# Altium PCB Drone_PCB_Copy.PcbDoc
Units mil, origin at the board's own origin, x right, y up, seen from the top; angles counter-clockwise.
Board outline 3300 x 3300 mil, 4 copper layers (Top Layer, Ground_Layer, Power_Layer, Bottom Layer), stack 40.247 mil thick; 10 components, 3 nets, 104 pads, 42 vias.
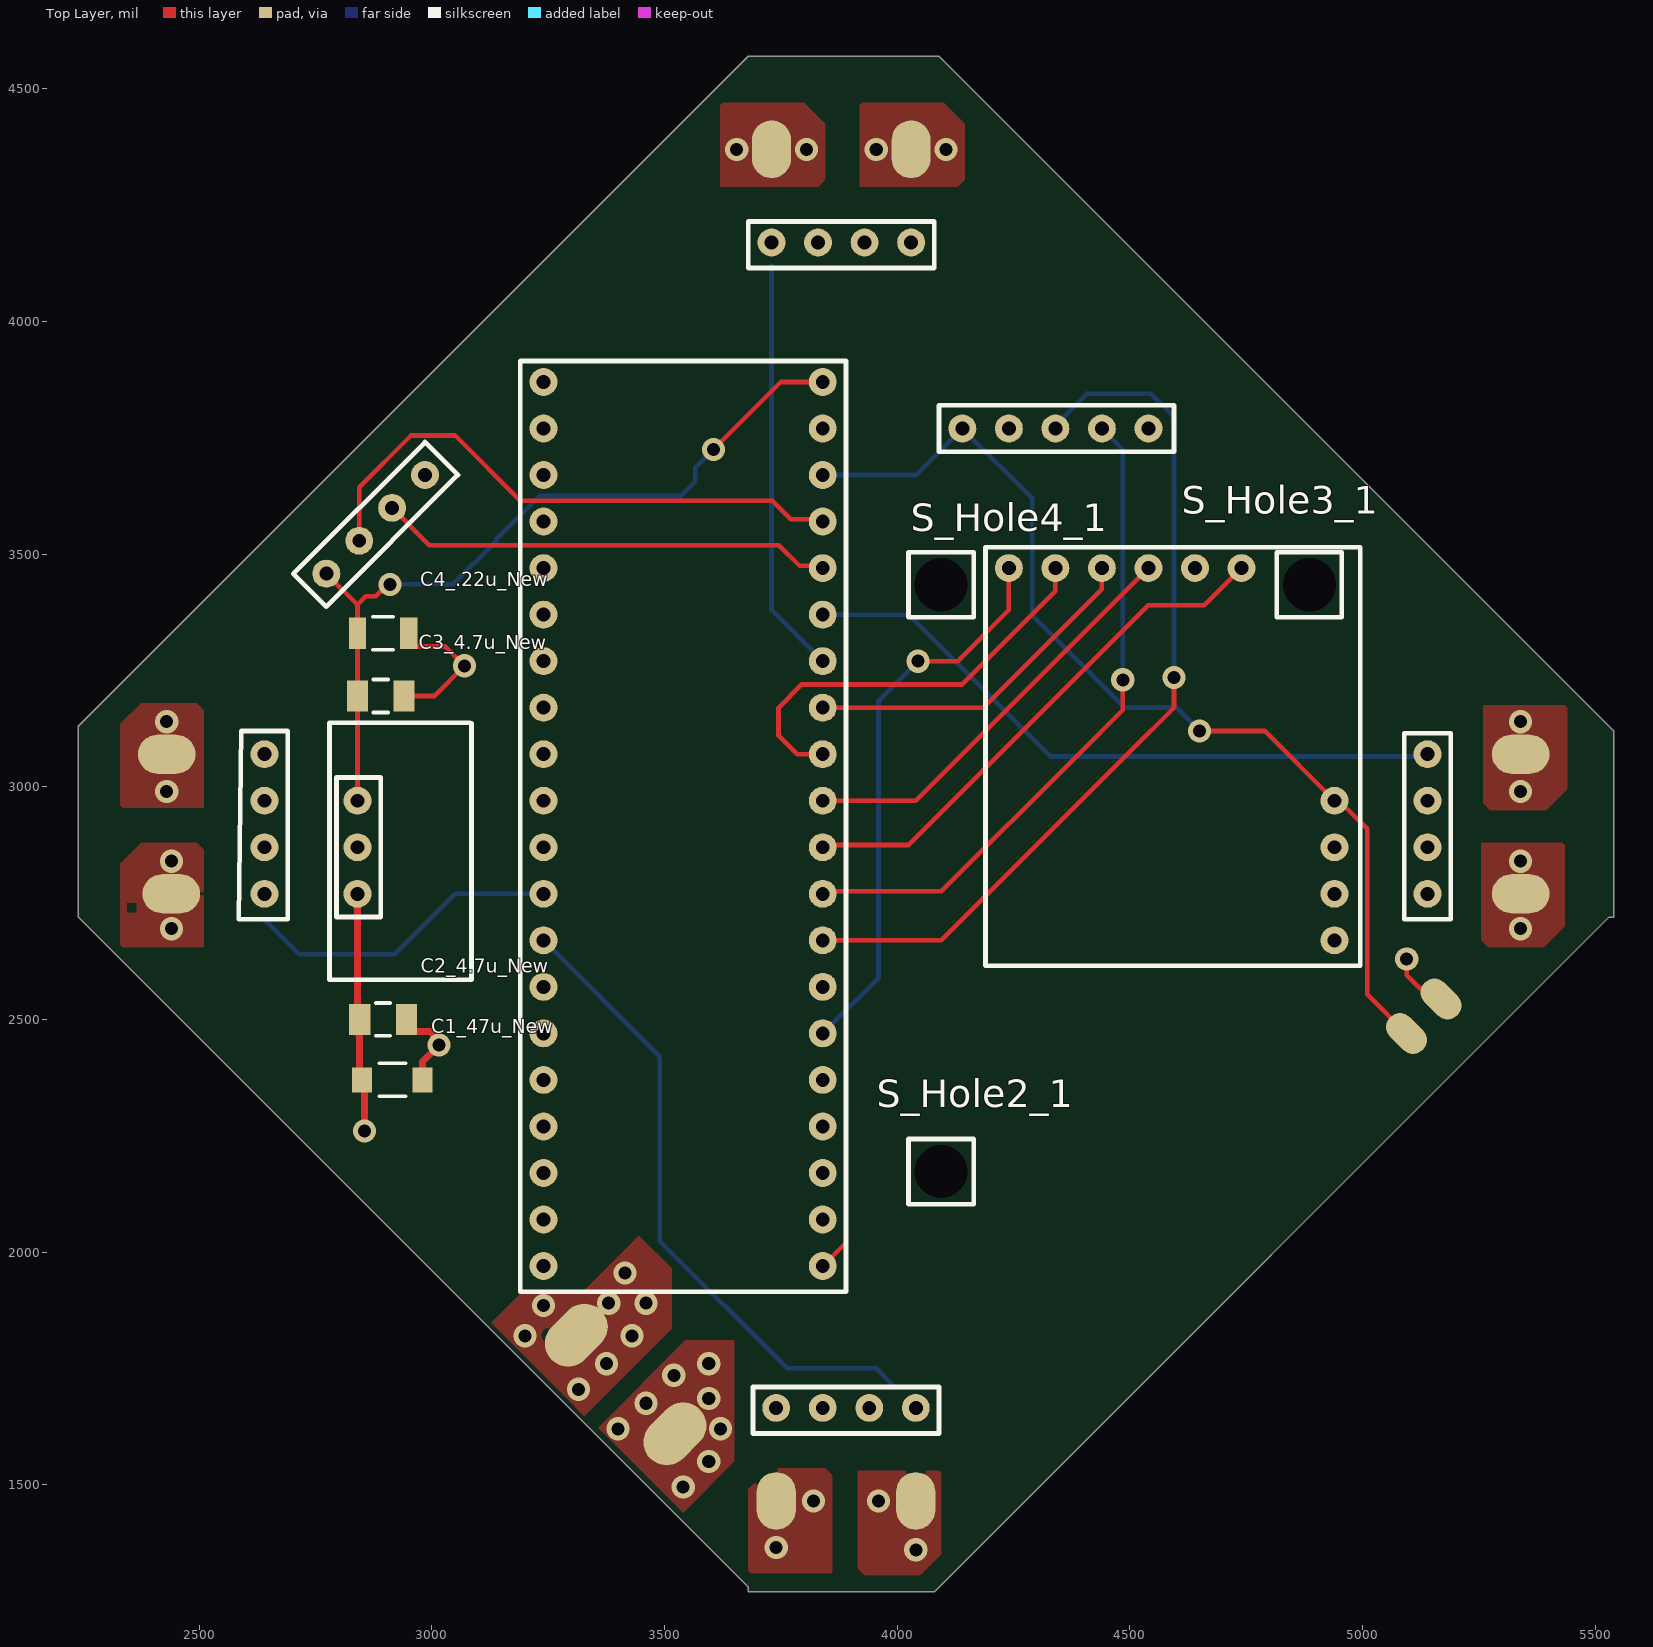
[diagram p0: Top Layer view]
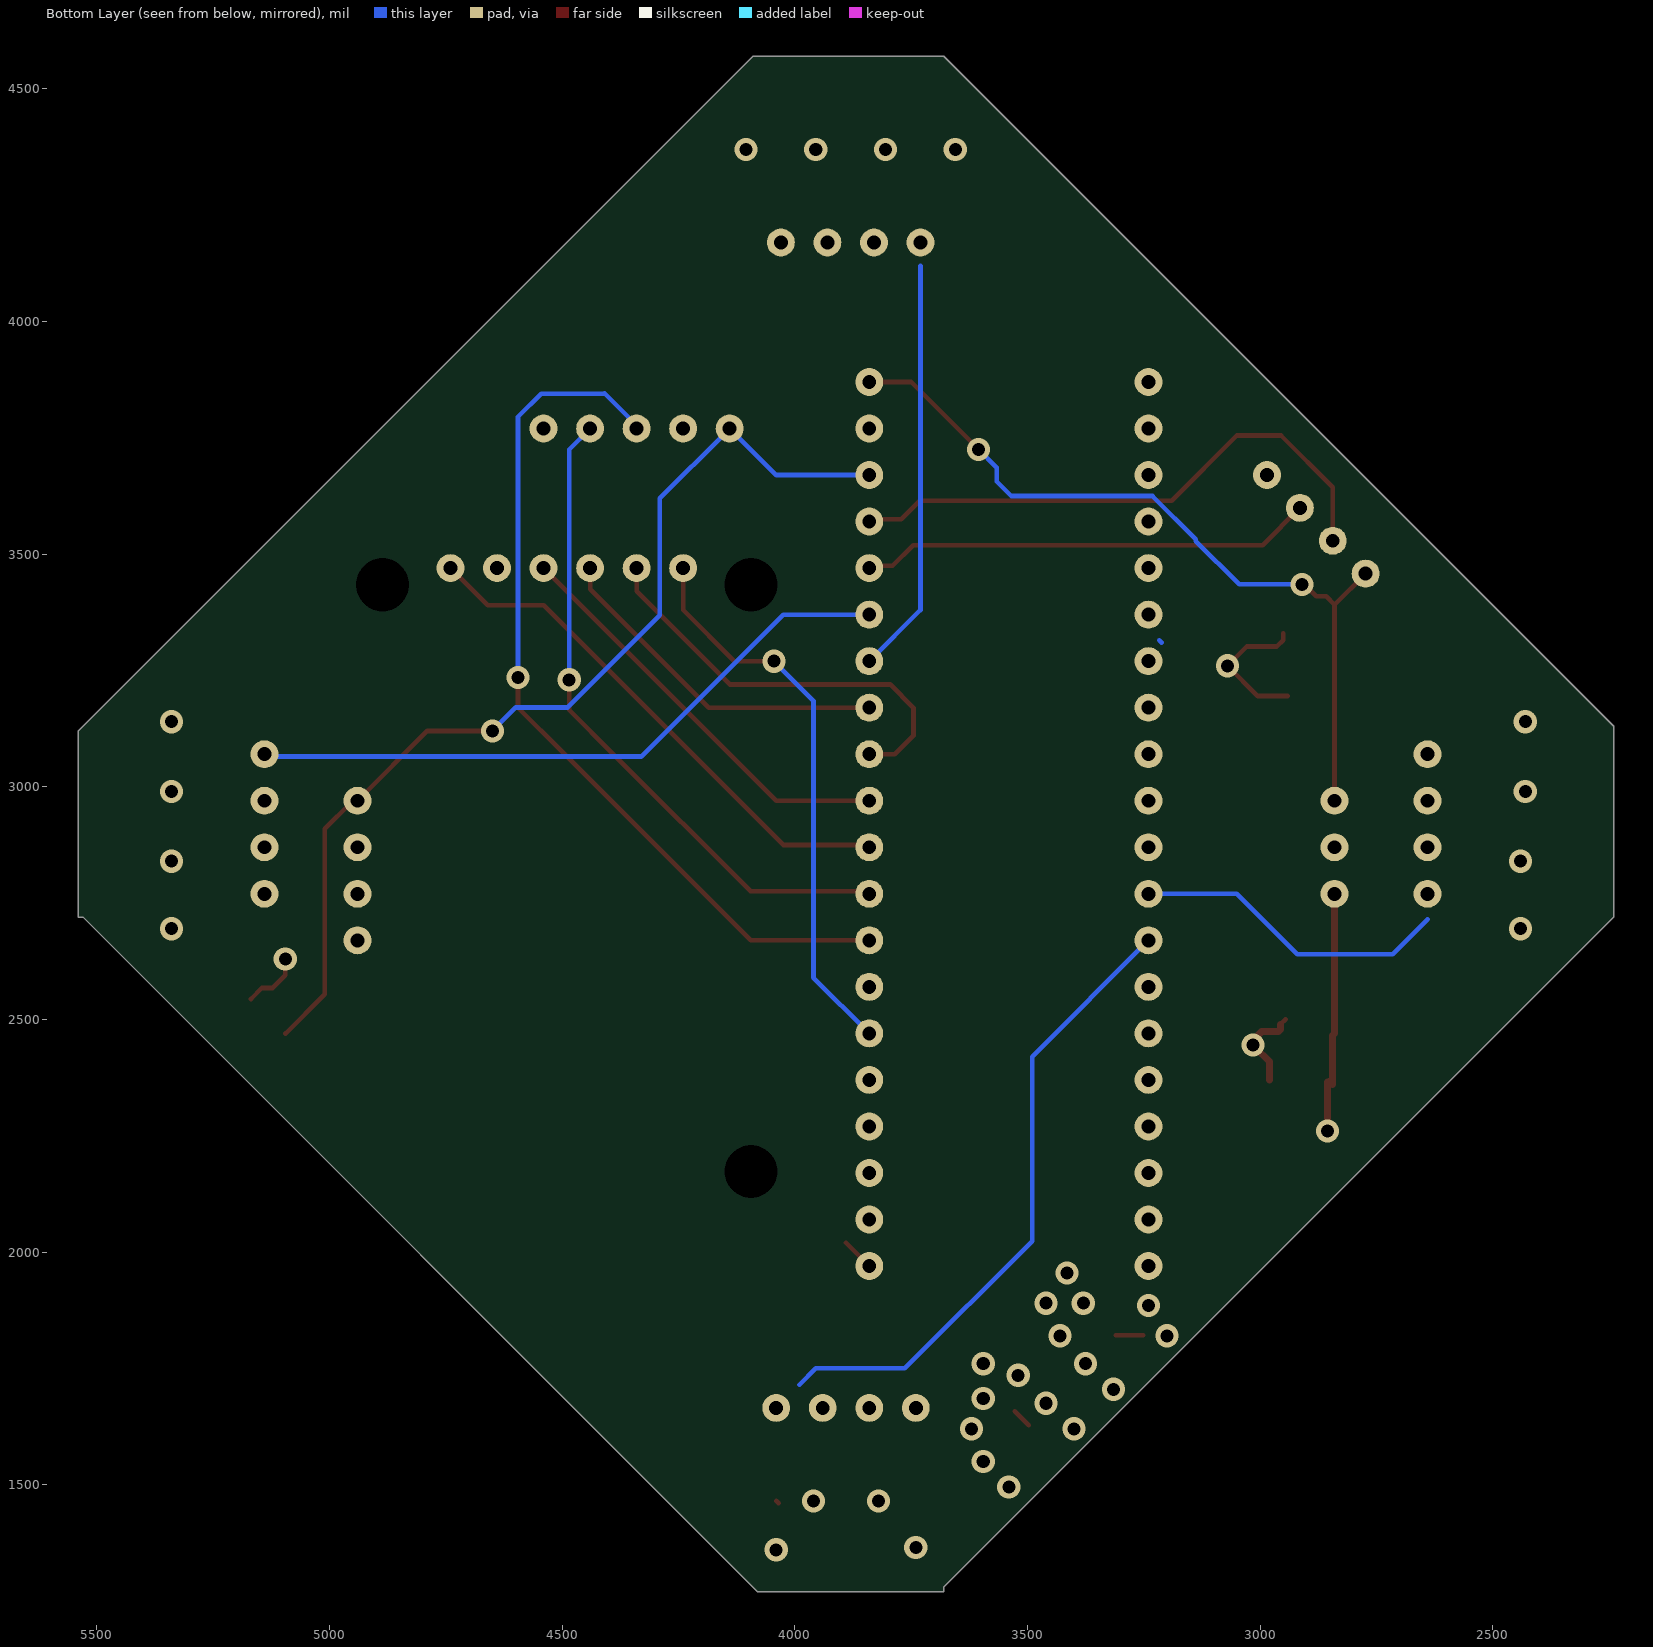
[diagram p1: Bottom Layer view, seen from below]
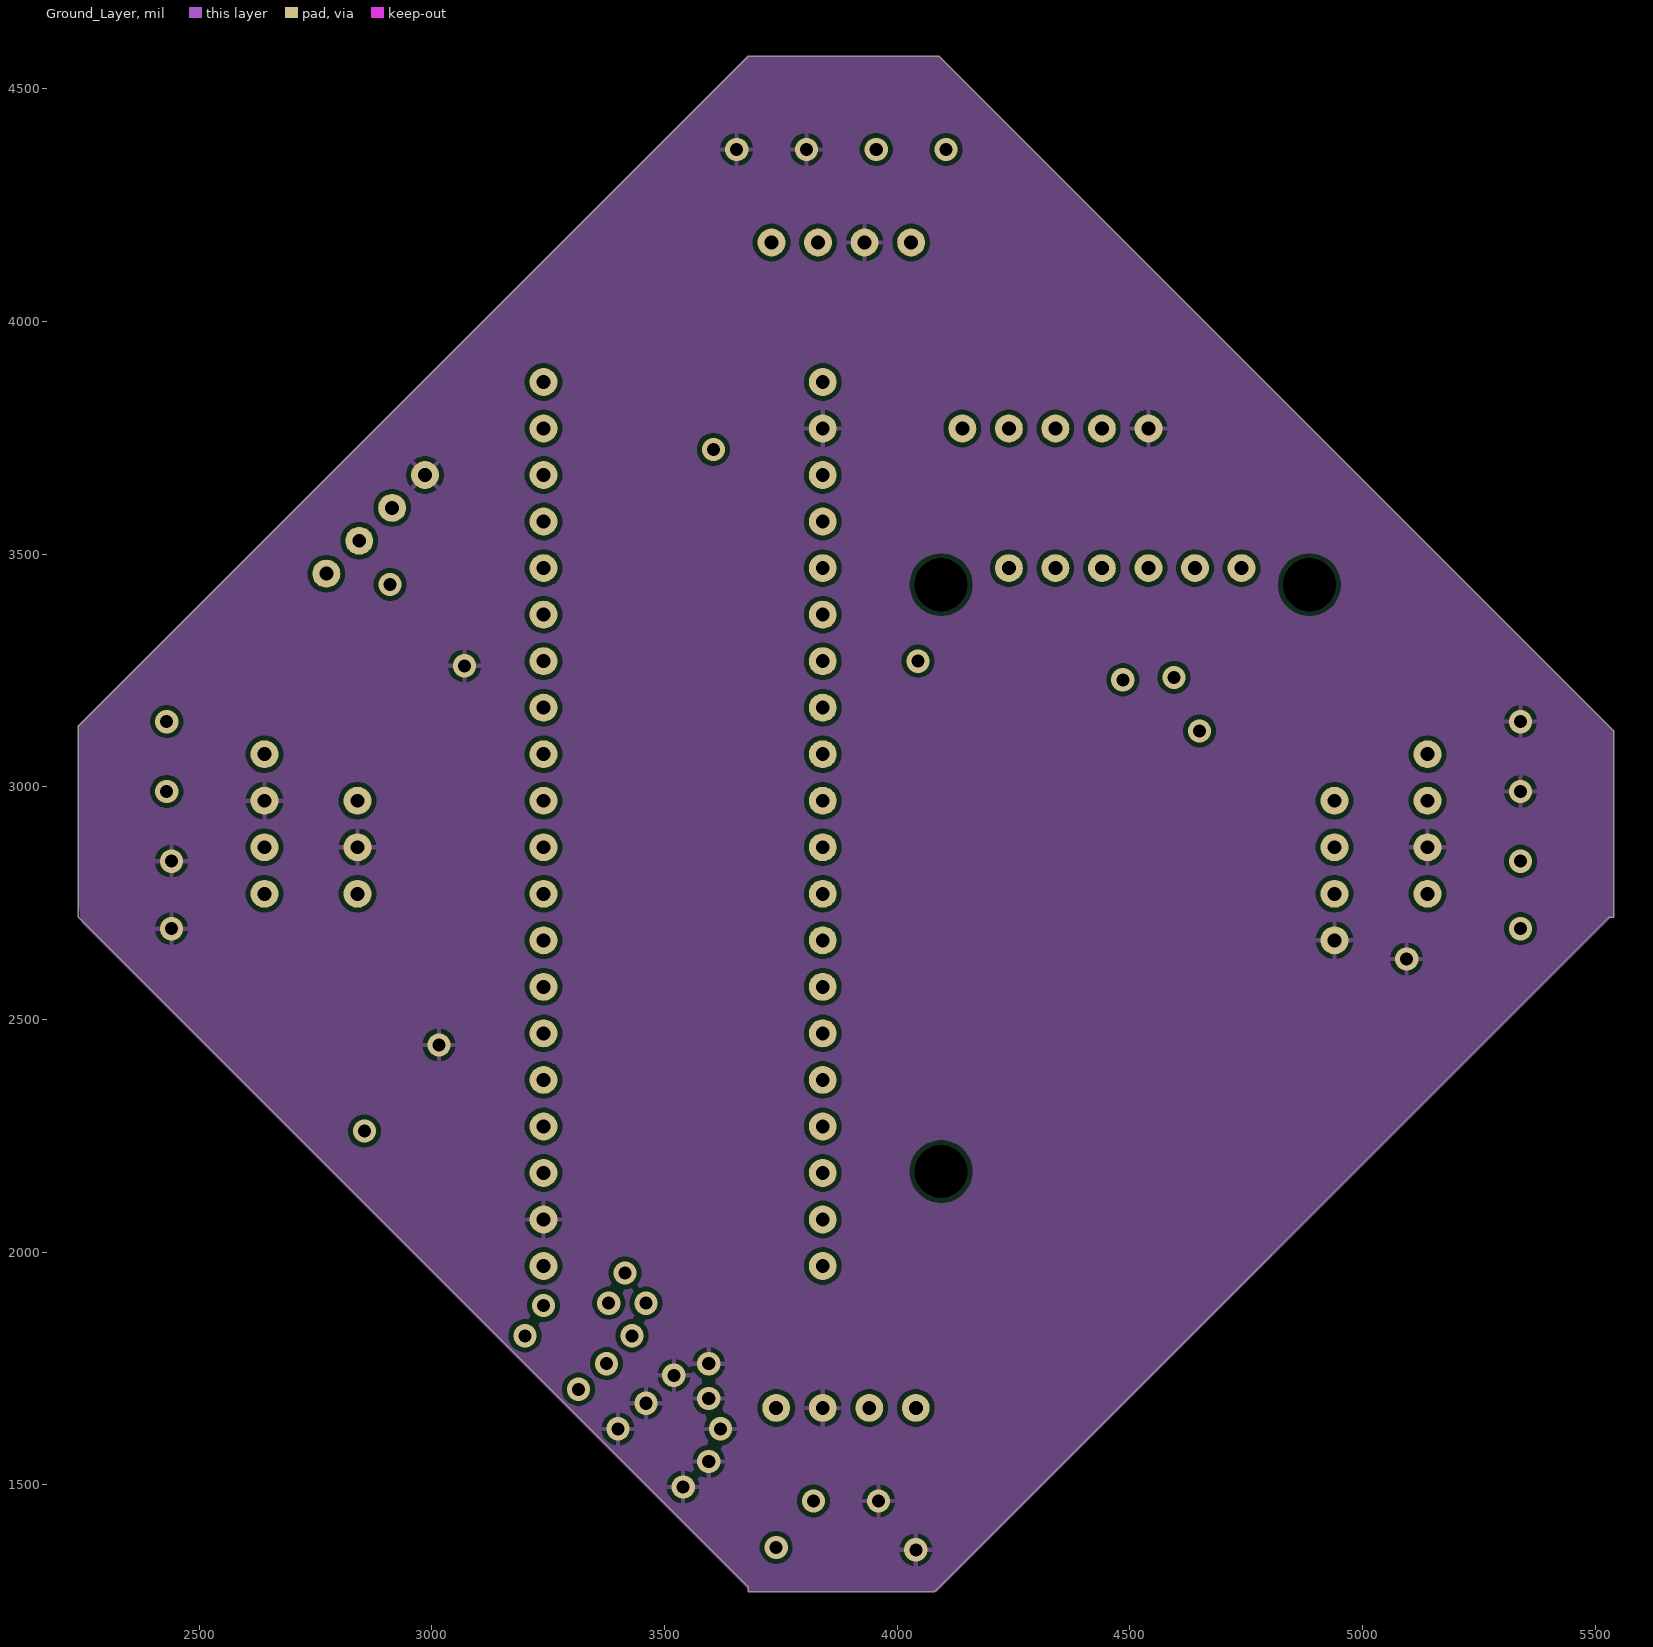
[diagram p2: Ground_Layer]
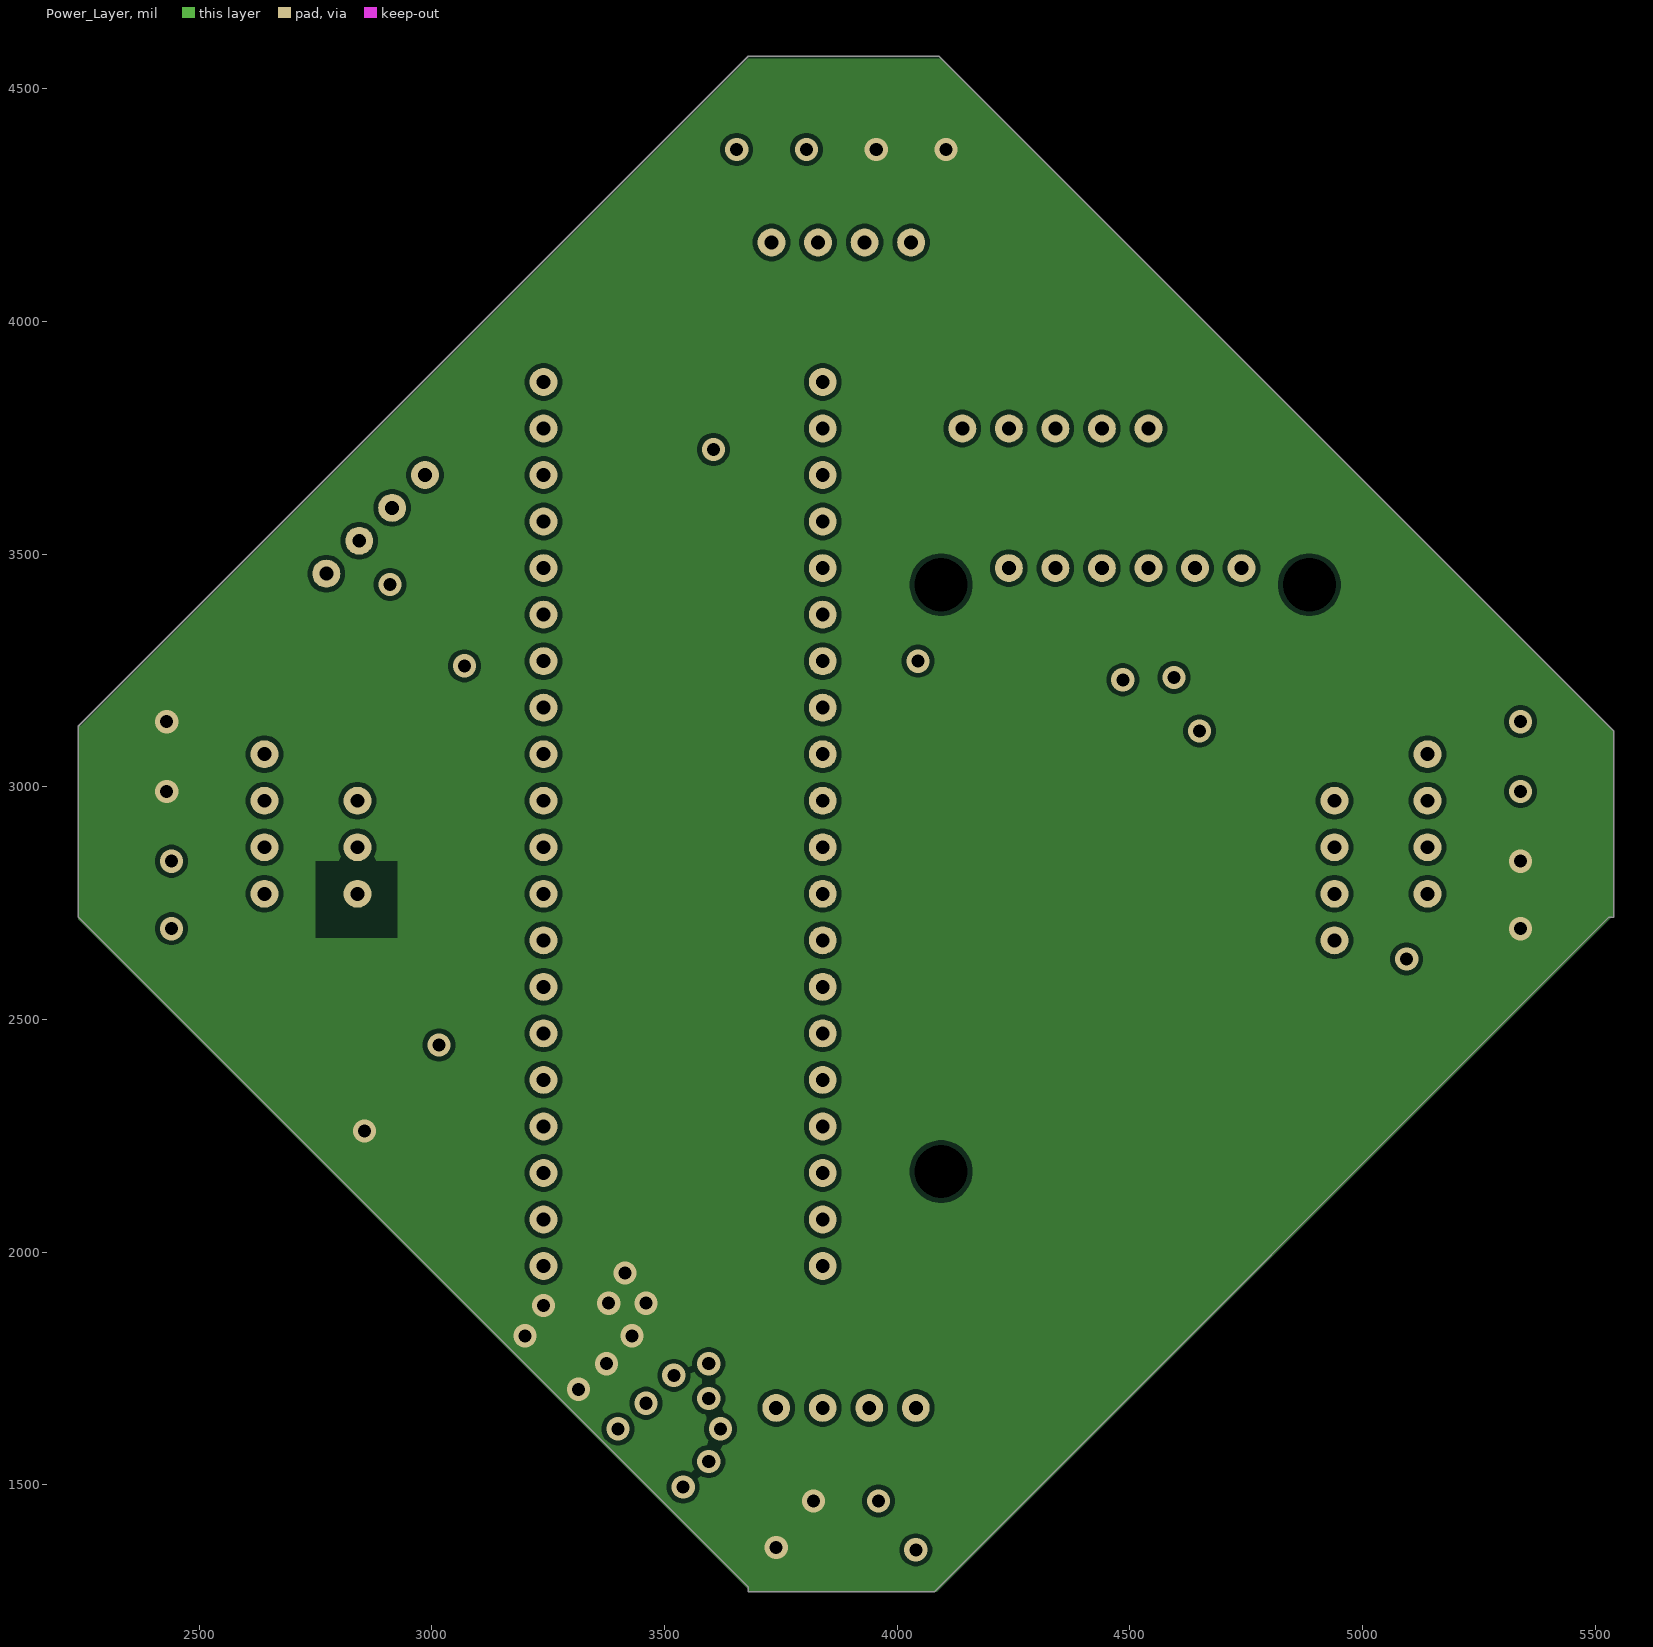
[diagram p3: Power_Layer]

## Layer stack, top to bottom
Top Solder: solder mask 0.4, Solder Resist, Dk 3.5
Top Layer: signal copper 5.5118
Dielectric 2: prepreg 2.8, PP-006, Dk 4.1
Ground_Layer: signal copper 5.5118
Dielectric 1: dielectric 12.6, FR-4, Dk 4.8
Power_Layer: signal copper 5.5118
Dielectric 3: prepreg 2.8, PP-006, Dk 4.1
Bottom Layer: signal copper 5.5118
Bottom Solder: solder mask 0.4, Solder Resist, Dk 3.5

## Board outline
2240,2720 3680,1280 3680,1270 4080,1270 5530,2720 5540,2720 5540,3120 4090,4570 3680,4570 2240,3130

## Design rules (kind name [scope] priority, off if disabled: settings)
Clearance [All] p1: gap=10 ignorepadtopadclearanceinfootprint=FALSE
PolygonConnect PolygonConnect_14 [All vs IsNamedPolygon('+12V_L01_P008')] p1: thpad.connectstyle=Direct thpad.reliefconductorwidth=10 thpad.reliefentries=4 thpad.polygonreliefangle="90 Angle" thpad.airgapwidth=10 smdpad.connectstyle=Relief smdpad.reliefconductorwidth=10 smdpad.reliefentries=4 smdpad.polygonreliefangle="90 Angle" smdpad.airgapwidth=10 via.connectstyle=Direct via.reliefconductorwidth=10 via.reliefentries=4 via.polygonreliefangle="90 Angle" via.airgapwidth=10
PolygonConnect PolygonConnect_13 [All vs IsNamedPolygon('GND_L01_P009')] p2: thpad.connectstyle=Relief thpad.reliefconductorwidth=10 thpad.reliefentries=4 thpad.polygonreliefangle="90 Angle" thpad.airgapwidth=10 smdpad.connectstyle=Relief smdpad.reliefconductorwidth=10 smdpad.reliefentries=4 smdpad.polygonreliefangle="90 Angle" smdpad.airgapwidth=10 via.connectstyle=Direct via.reliefconductorwidth=10 via.reliefentries=4 via.polygonreliefangle="90 Angle" via.airgapwidth=10
PolygonConnect PolygonConnect_12 [All vs IsNamedPolygon('+12V_L01_P010')] p3: thpad.connectstyle=Relief thpad.reliefconductorwidth=10 thpad.reliefentries=4 thpad.polygonreliefangle="90 Angle" thpad.airgapwidth=10 smdpad.connectstyle=Relief smdpad.reliefconductorwidth=10 smdpad.reliefentries=4 smdpad.polygonreliefangle="90 Angle" smdpad.airgapwidth=10 via.connectstyle=Direct via.reliefconductorwidth=10 via.reliefentries=4 via.polygonreliefangle="90 Angle" via.airgapwidth=10
PolygonConnect PolygonConnect_11 [All vs IsNamedPolygon('GND_L01_P015')] p4: thpad.connectstyle=Relief thpad.reliefconductorwidth=10 thpad.reliefentries=4 thpad.polygonreliefangle="90 Angle" thpad.airgapwidth=10 smdpad.connectstyle=Relief smdpad.reliefconductorwidth=10 smdpad.reliefentries=4 smdpad.polygonreliefangle="90 Angle" smdpad.airgapwidth=10 via.connectstyle=Direct via.reliefconductorwidth=10 via.reliefentries=4 via.polygonreliefangle="90 Angle" via.airgapwidth=10
PolygonConnect PolygonConnect_10 [All vs IsNamedPolygon('GND_L01_P012')] p5: thpad.connectstyle=Relief thpad.reliefconductorwidth=10 thpad.reliefentries=4 thpad.polygonreliefangle="90 Angle" thpad.airgapwidth=10 smdpad.connectstyle=Relief smdpad.reliefconductorwidth=10 smdpad.reliefentries=4 smdpad.polygonreliefangle="90 Angle" smdpad.airgapwidth=10 via.connectstyle=Direct via.reliefconductorwidth=10 via.reliefentries=4 via.polygonreliefangle="90 Angle" via.airgapwidth=10
PolygonConnect PolygonConnect_9 [All vs IsNamedPolygon('GND_L01_P011')] p6: thpad.connectstyle=Relief thpad.reliefconductorwidth=10 thpad.reliefentries=4 thpad.polygonreliefangle="90 Angle" thpad.airgapwidth=10 smdpad.connectstyle=Relief smdpad.reliefconductorwidth=10 smdpad.reliefentries=4 smdpad.polygonreliefangle="90 Angle" smdpad.airgapwidth=10 via.connectstyle=Direct via.reliefconductorwidth=10 via.reliefentries=4 via.polygonreliefangle="90 Angle" via.airgapwidth=10
PolygonConnect PolygonConnect_8 [All vs IsNamedPolygon('+12V_L01_P014')] p7: thpad.connectstyle=Relief thpad.reliefconductorwidth=10 thpad.reliefentries=4 thpad.polygonreliefangle="90 Angle" thpad.airgapwidth=10 smdpad.connectstyle=Relief smdpad.reliefconductorwidth=10 smdpad.reliefentries=4 smdpad.polygonreliefangle="90 Angle" smdpad.airgapwidth=10 via.connectstyle=Direct via.reliefconductorwidth=10 via.reliefentries=4 via.polygonreliefangle="90 Angle" via.airgapwidth=10
PolygonConnect PolygonConnect_7 [All vs IsNamedPolygon('+12V_L01_P013')] p8: thpad.connectstyle=Relief thpad.reliefconductorwidth=10 thpad.reliefentries=4 thpad.polygonreliefangle="90 Angle" thpad.airgapwidth=10 smdpad.connectstyle=Relief smdpad.reliefconductorwidth=10 smdpad.reliefentries=4 smdpad.polygonreliefangle="90 Angle" smdpad.airgapwidth=10 via.connectstyle=Direct via.reliefconductorwidth=10 via.reliefentries=4 via.polygonreliefangle="90 Angle" via.airgapwidth=10
PolygonConnect PolygonConnect_6 [All vs IsNamedPolygon('+12V_L03_P001')] p9: thpad.connectstyle=Relief thpad.reliefconductorwidth=10 thpad.reliefentries=4 thpad.polygonreliefangle="90 Angle" thpad.airgapwidth=10 smdpad.connectstyle=Relief smdpad.reliefconductorwidth=10 smdpad.reliefentries=4 smdpad.polygonreliefangle="90 Angle" smdpad.airgapwidth=10 via.connectstyle=Direct via.reliefconductorwidth=10 via.reliefentries=4 via.polygonreliefangle="90 Angle" via.airgapwidth=10
PolygonConnect PolygonConnect_5 [All vs IsNamedPolygon('GND_L01_P003')] p10: connectstyle=Direct reliefconductorwidth=10 reliefentries=4 polygonreliefangle="90 Angle" airgapwidth=10
PolygonConnect Polygon_Direct2 [All vs IsNamedPolygon('GND_L01_P003')] p11: thpad.connectstyle=Direct thpad.reliefconductorwidth=10 thpad.reliefentries=4 thpad.polygonreliefangle="90 Angle" thpad.airgapwidth=10 smdpad.connectstyle=Relief smdpad.reliefconductorwidth=10 smdpad.reliefentries=4 smdpad.polygonreliefangle="90 Angle" smdpad.airgapwidth=10 via.connectstyle=Direct via.reliefconductorwidth=10 via.reliefentries=4 via.polygonreliefangle="90 Angle" via.airgapwidth=10
PolygonConnect Polygon_Direct [All vs IsNamedPolygon('+12V_L01_P002')] p12: connectstyle=Direct reliefconductorwidth=10 reliefentries=4 polygonreliefangle="90 Angle" airgapwidth=10
PolygonConnect PolygonConnect_4 [All vs IsNamedPolygon('+12V_L01_P002')] p13: connectstyle=Direct reliefconductorwidth=10 reliefentries=4 polygonreliefangle="90 Angle" airgapwidth=10
PolygonConnect PolygonConnect_3 [All vs IsNamedPolygon('+12V_L01_P002')] p14: thpad.connectstyle=Direct thpad.reliefconductorwidth=10 thpad.reliefentries=4 thpad.polygonreliefangle="90 Angle" thpad.airgapwidth=10 smdpad.connectstyle=Relief smdpad.reliefconductorwidth=10 smdpad.reliefentries=4 smdpad.polygonreliefangle="90 Angle" smdpad.airgapwidth=10 via.connectstyle=Direct via.reliefconductorwidth=10 via.reliefentries=4 via.polygonreliefangle="90 Angle" via.airgapwidth=10
PolygonConnect PolygonConnect_2 [All vs IsNamedPolygon('GND_L01_P003')] p15: thpad.connectstyle=Direct thpad.reliefconductorwidth=10 thpad.reliefentries=4 thpad.polygonreliefangle="90 Angle" thpad.airgapwidth=10 smdpad.connectstyle=Relief smdpad.reliefconductorwidth=10 smdpad.reliefentries=4 smdpad.polygonreliefangle="90 Angle" smdpad.airgapwidth=10 via.connectstyle=Relief via.reliefconductorwidth=10 via.reliefentries=4 via.polygonreliefangle="90 Angle" via.airgapwidth=10
PolygonConnect PolygonConnect_1 [All vs IsNamedPolygon('+12V_L01_P002')] p16: thpad.connectstyle=Direct thpad.reliefconductorwidth=10 thpad.reliefentries=4 thpad.polygonreliefangle="90 Angle" thpad.airgapwidth=10 smdpad.connectstyle=Relief smdpad.reliefconductorwidth=10 smdpad.reliefentries=4 smdpad.polygonreliefangle="90 Angle" smdpad.airgapwidth=10 via.connectstyle=Relief via.reliefconductorwidth=10 via.reliefentries=4 via.polygonreliefangle="90 Angle" via.airgapwidth=10
PolygonConnect [All] p17: connectstyle=Relief reliefconductorwidth=10 reliefentries=4 polygonreliefangle="90 Angle" airgapwidth=10
RoutingVias [All] p1: holewidth=28 width=50 viastyle="Through Hole" minholewidth=28 minwidth=50 maxholewidth=28 maxwidth=50
SolderMaskExpansion [All] p1: expansion=4 istentingtop=FALSE
SupplyNets "Schematic Supply Nets_4" [InNet('+12V')] p1: voltage=0.000
SupplyNets "Schematic Supply Nets_3" [InNet('+12')] p2: voltage=0.000
SupplyNets "Schematic Supply Nets_2" [InNet('+3V3')] p3: voltage=0.000
SupplyNets "Schematic Supply Nets_1" [InNet('GND')] p4: voltage=0.000
SupplyNets "Schematic Supply Nets" [InNet('3V3')] p5: voltage=0.000
Width [All] p1: maxlimit=100 minlimit=10 preferedwidth=10 midlayer1_maxwidth=10 midlayer2_maxwidth=10 bottomlayer_maxwidth=10 minimp=50.000000 maximp=50.000000 favimp=50.000000
30 further rules are at their usual default settings.

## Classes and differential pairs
component class Schematic: U?

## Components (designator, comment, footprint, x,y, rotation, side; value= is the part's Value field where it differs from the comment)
C1_47u_New "Comment" FP-C3216-160-0_2-MFG 2915,2370 r0 top
C2_4.7u_New "Comment" FP-GRM31C-0_2-e0_3_0_8-IPC_C 2895,2500 r0 top
C3_4.7u_New "Comment" FP-GRM31C-0_2-e0_3_0_8-IPC_C 2890,3195 r0 top
C4_.22u_New "Comment" FP-C1206C-EB-MFG 2895.12,3330 r0 top
S_Hole2 "Comment" MountingHole_3.2mm 10348.66,-331.14 r180 top
S_Hole2_1 "Comment" MountingHole_3.2mm 4094.49,2172.87 r180 top
S_Hole3 "Comment" MountingHole_3.2mm 11124.25,930.28 r180 top
S_Hole3_1 "Comment" MountingHole_3.2mm 4885.83,3434.29 r180 top
S_Hole4 "Comment" MountingHole_3.2mm 10336.85,930.28 r180 top
S_Hole4_1 "Comment" MountingHole_3.2mm 4094.49,3434.29 r180 top

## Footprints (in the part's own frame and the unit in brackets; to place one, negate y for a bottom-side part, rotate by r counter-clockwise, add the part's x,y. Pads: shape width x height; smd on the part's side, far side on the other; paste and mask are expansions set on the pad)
FP-C1206C-EB-MFG [mm]
  rect 0.95x1.7 smd paste+0 mask+0: 1(-1.4,0) 2(1.4,0)
  silkscreen extent -0.55,-0.9 0.55,0.9, body extent -2,-1 2,1, height 0.25
FP-C3216-160-0_2-MFG [mm]
  rect 1.1x1.35 smd paste+0 mask+0: 1(-1.65,0) 2(1.65,0)
  silkscreen extent -0.72,-0.9 0.72,0.9, body extent -2.3,-1 2.3,1, height 0.25
FP-GRM31C-0_2-e0_3_0_8-IPC_C [mil]
  rect 45.46x67.17 smd paste+0 mask+0: 1(-50.23,0) 2(50.23,0)
  silkscreen extent -16,-35 16,35, body extent -77,-39 77,39, height 10
MountingHole_3.2mm [mm]
  round 1 hole 2.9: ""(0,0)
  silkscreen extent -1.78,-1.78 1.78,1.78

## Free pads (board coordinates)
  oval 150x100 smd rot 45: 12V_P(3310.25,1821.38) GND_P(3522.38,1609.25)
  round 60 hole 30: 127(2640,2770) 127(2640,2870) 127(2640,2970) 127(2640,3070) 129(4140,3770) 129(4240,3770) 129(4340,3770) 129(4440,3770) 129(4540,3770) 131(2773.08,3458.08) 131(2843.79,3528.79) 131(2914.5,3599.5) 131(2985.21,3670.21) 132(3240,1970) 132(3240,2070) 132(3240,2170) 132(3240,2270) 132(3240,2370) 132(3240,2470) 132(3240,2570) 132(3240,2670) 132(3240,2770) 132(3240,2870) 132(3240,2970) 132(3240,3070) 132(3240,3170) 132(3240,3270) 132(3240,3370) 132(3240,3470) 132(3240,3570) 132(3240,3670) 132(3240,3770) 132(3240,3870) 137(3730,4170) 137(3740,1665) 138(3830,4170) 138(3840,1665) 138(3840,1970) 138(3840,2070) 138(3840,2170) 138(3840,2270) 138(3840,2370) 138(3840,2470) 138(3840,2570) 138(3840,2670) 138(3840,2770) 138(3840,2870) 138(3840,2970) 138(3840,3070) 138(3840,3170) 138(3840,3270) 138(3840,3370) 138(3840,3470) 138(3840,3570) 138(3840,3670) 138(3840,3770) 138(3840,3870) 139(3930,4170) 139(3940,1665) 140(4030,4170) 140(4040,1665) 141(2840,2770) 141(2840,2870) 141(2840,2970) 141(4940,2670) 141(4940,2770) 141(4940,2870) 141(4940,2970) 143(4240,3470) 144(4340,3470) 145(4440,3470) 146(4540,3470) 147(4640,3470) 148(4740,3470) 150(5140,2770) 150(5140,2870) 150(5140,2970) 150(5140,3070)
  oval 100x60 smd rot 135: Cam_G(5168.89,2543.89) Cam_P(5094.64,2469.64)
  oval 124x84 smd: G_M1(2440,2770) G_M3(5340,3070) P_M1(2430,3070) P_M3(5340,2770)
  oval 84x124 smd: G_M2(3730,4370) G_M4(4040,1465) P_M2(4030,4370) P_M4(3740,1465)

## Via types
v1: diameter 50, hole 28, Top Layer to Bottom Layer, 42 vias

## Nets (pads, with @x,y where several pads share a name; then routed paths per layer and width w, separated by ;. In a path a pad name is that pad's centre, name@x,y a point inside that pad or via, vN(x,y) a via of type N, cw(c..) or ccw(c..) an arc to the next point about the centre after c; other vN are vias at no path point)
+3V3: 
+12V: C1_47u_New.1 C2_4.7u_New.1 pad.12V_P pad.141@2840,2770 pad.P_M1 pad.P_M2 pad.P_M3 pad.P_M4 | length 583.7
  Top Layer w10: C2_4.7u_New.1@2840,2469.77 2844.77,2465 ; C1_47u_New.1 C1_47u_New.1@2855,2365.04 ; pad.12V_P@3251,1820.92 3309.79,1820.92 pad.12V_P
  Top Layer w15: C2_4.7u_New.1@2840,2469.77 pad.141@2840,2770 ; C1_47u_New.1@2844.77,2359.77 2844.77,2465 ; v1(2855,2260) C1_47u_New.1@2855,2365.04
  other v1: 3740,1365 3820,1465 3315,1705 3375,1760 3200,1820 3430,1820 3240,1885 3380,1890 3460,1890 3415,1955 5340,2695 5340,2840 2430,2990 2430,3140 3955,4370 4105,4370
GND: C1_47u_New.2 C2_4.7u_New.2 C3_4.7u_New.2 C4_.22u_New.2 pad.127@2640,2970 pad.129@4540,3770 pad.131@2985.21,3670.21 pad.132@3240,2070 pad.138@3840,1665 pad.138@3840,3770 pad.139@3930,4170 pad.141@2840,2870 pad.141@4940,2670 pad.150@5140,2870 pad.Cam_G pad.G_M1 pad.G_M2 pad.G_M3 pad.G_M4 pad.GND_P | length 668.7
  Top Layer w10: C3_4.7u_New.2 3005,3195 v1(3070,3260) 3028.46,3301.54 2963.94,3301.54 2950.24,3315.24 C4_.22u_New.2 ; C2_4.7u_New.2 C2_4.7u_New.2@2956.09,2489.14 ; pad.GND_P@3497.5,1627.5 pad.GND_P@3527.65,1657.65 ; pad.G_M4@4035,1460 pad.G_M4 ; v1(5095,2630) 5095,2595 5122.4,2567.6 5145.18,2567.6 pad.Cam_G
  Top Layer w15: C2_4.7u_New.2@2956.09,2489.14 2956.09,2478.28 2960.46,2473.91 2996.44,2473.91 v1@3013.3,2457.05 ; C1_47u_New.2 2979.96,2409.43 v1@3010.49,2439.96
  other v1: 4040,1360 3960,1465 3540,1495 3595,1550 3400,1620 3620,1620 3460,1675 3595,1685 3520,1735 3595,1760 3015,2445 2440,2695 2440,2840 5340,2990 5340,3140 3655,4370 3805,4370
pads on no net: C3_4.7u_New.1 C4_.22u_New.1 S_Hole2. S_Hole2_1. S_Hole3. S_Hole3_1. S_Hole4. S_Hole4_1.
copper on no net: | length 18805.7
  Top Layer w10: 2773.08,3458.08 2840,3391.15 ; 2840,2970 2840,3391.15 ; 2843.79,3528.79 2843.79,3643.79 2955,3755 3050,3755 3190,3615 3731.36,3615 3771.36,3575 3815,3575 3825,3565 ; v1(2910,3435) 2904.93,3435 2879.18,3409.25 2858.1,3409.25 2840,3391.15 ; 2914.5,3599.5 2994.5,3519.5 3745.5,3519.5 3790,3475 3820,3475 ; 3215,2270 3240,2270 ; v1(3605,3725) 3750,3870 3840,3870 ; 3840,1970 3890,2020 ; 3840,2670 4095,2670 4500,3075 4595,3170 v1(4595,3235) ; 3840,2875 4025,2875 4540,3390 4660,3390 4740,3470 ; 3840,3070 3785,3070 3745,3110 3745,3170 3795,3220 4140,3220 4340,3420 4340,3470 ; 3849.57,2760.43 3840,2770 3845.19,2775.19 4095.19,2775.19 4390,3070 4485,3165 v1(4485,3230) ; 3850,2970 4040,2970 4540,3470 ; 3870,3170 4185,3170 4440,3425 4440,3470 ; v1(4045,3270) 4130,3270 4240,3380 4240,3470 ; v1(4650,3120) 4790,3120 4940,2970 ; 4950,2965 4955,2965 5010,2910 5010,2554.29 5094.64,2469.64
  Bottom Layer w10: 2640,2715 2715,2640 2920,2640 3050,2770 3240,2770 ; v1(2910,3435) 2950,3435 3045,3435 3138.18,3528.18 3138.18,3531.82 3231.36,3625 3535,3625 3566.17,3656.17 3566.17,3686.17 v1(3605,3725) ; 3211.82,3310 3216.82,3315 ; 3240,2670 3490,2420 3490,2023.49 3763.49,1750 3955,1750 3990,1715 ; 3730,4120 3730,3380 3840,3270 ; 3840,2470 3960,2590 3960,2770 3960,2835 3960,3185 v1(4045,3270) ; 3840,3370 4025,3370 4330,3065 5140,3065 ; 3840,3670 4040,3670 4140,3770 ; 4150,3760 4290,3620 4290,3368.43 4487.89,3170.54 4599.46,3170.54 v1(4650,3120) ; 4336.64,3773.36 4409.14,3845.86 4410,3845 4545,3845 4595,3795 v1(4595,3235) ; 4440,3770 4485,3725 v1(4485,3230)

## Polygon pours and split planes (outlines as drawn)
+12V on Top Layer "+12V_L01_P002" (solid, pour order 2): 3127.5,1847.5 3190,1910 3320,1910 3445,2035 3515,1965 3515,1835 3327.5,1647.5 3285,1690
GND on Top Layer "GND_L01_P011" (solid, pour order 11): 5440,2995 5395,2950 5275,2950 5260,2965 5260,3175 5435,3175 5440,3170
GND on Top Layer "GND_L01_P015" (solid, pour order 15): 2330,2835 2375,2880 2495,2880 2510,2865 2510,2655 2335,2655 2330,2660
+12V on Top Layer "+12V_L01_P014" (solid, pour order 14): 2330,3135 2375,3180 2495,3180 2510,3165 2510,2955 2335,2955 2330,2960
+12V on Top Layer "+12V_L01_P013" (solid, pour order 13): 4100,4470 4145,4425 4145,4305 4130,4290 3920,4290 3920,4465 3925,4470
GND on Top Layer "GND_L01_P012" (solid, pour order 12): 3800,4470 3845,4425 3845,4305 3830,4290 3620,4290 3620,4465 3625,4470
+12V on Top Layer "+12V_L01_P010" (solid, pour order 10): 5435,2700 5390,2655 5270,2655 5255,2670 5255,2880 5430,2880 5435,2875
GND on Top Layer "GND_L01_P009" (solid, pour order 9): 4095,1350 4050,1305 3930,1305 3915,1320 3915,1530 4090,1530 4095,1525
+12V on Top Layer "+12V_L01_P008" (solid, pour order 8): 3680,1490 3725,1535 3845,1535 3860,1520 3860,1310 3685,1310 3680,1315
GND on Top Layer "GND_L01_P003" (solid, pour order 3): 3357.5,1622.5 3545,1810 3650,1810 3650,1550 3540,1440
GND on Ground_Layer "GND_L02_P000" (solid, pour order 0): 2240,2770 2240,2795 2240,2715 3685,1270 4085,1270 5540,2725 5540,3120 4090,4570 3680,4570 2240,3130 2240,2720 2245,2715
+12V on Power_Layer "+12V_L03_P001" (solid, pour order 1): 2240,3130 2245,3130 3680,4565 4095,4565 5540,3120 5540,2725 4085,1270 3685,1270 2240,2715

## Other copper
Top Layer:
Power_Layer:
  pour cut-out: 2750,2840 2925,2840 2925,2675 2750,2675

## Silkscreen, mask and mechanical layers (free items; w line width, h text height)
Top Overlay:
  lines w10: 3082.52,2585 2780,2585 2780,3137.48 3082.48,3137.48 ; 3085,2585 3085,3136.18 ; 2585,2715 2590,3120 2690,3120 2690,2715 2585,2715 ; 2702.37,3458.08 2773.08,3387.37 3055.92,3670.21 2985.21,3740.92 2702.37,3458.08 ; 2795,2720 2795,3020 2890,3020 2890,2720 2795,2720 ; 3190,1915 3890,1915 3890,3915 3190,3915 3190,1915 ; 3680,4115 4080,4115 4080,4215 3680,4215 3680,4115 ; 3690,1610 4090,1610 4090,1710 3690,1710 3690,1610 ; 4090,3720 4090,3820 4495,3820 4595,3820 4595,3720 4090,3720 ; 4190,2615 4995,2615 4995,3515 4190,3515 4190,2615 ; 5090,2715 5190,2715 5190,3115 5090,3115 5090,2715
Mechanical 1:
  lines w25: 3680,1270 4080,1270 5530,2720 5540,2720 5540,3120 4090,4570 ; 3680,1280 2240,2720 2240,3120 2240,3130 3680,4570 4080,4570 4090,4570 ; 4085,4570 4090,4570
